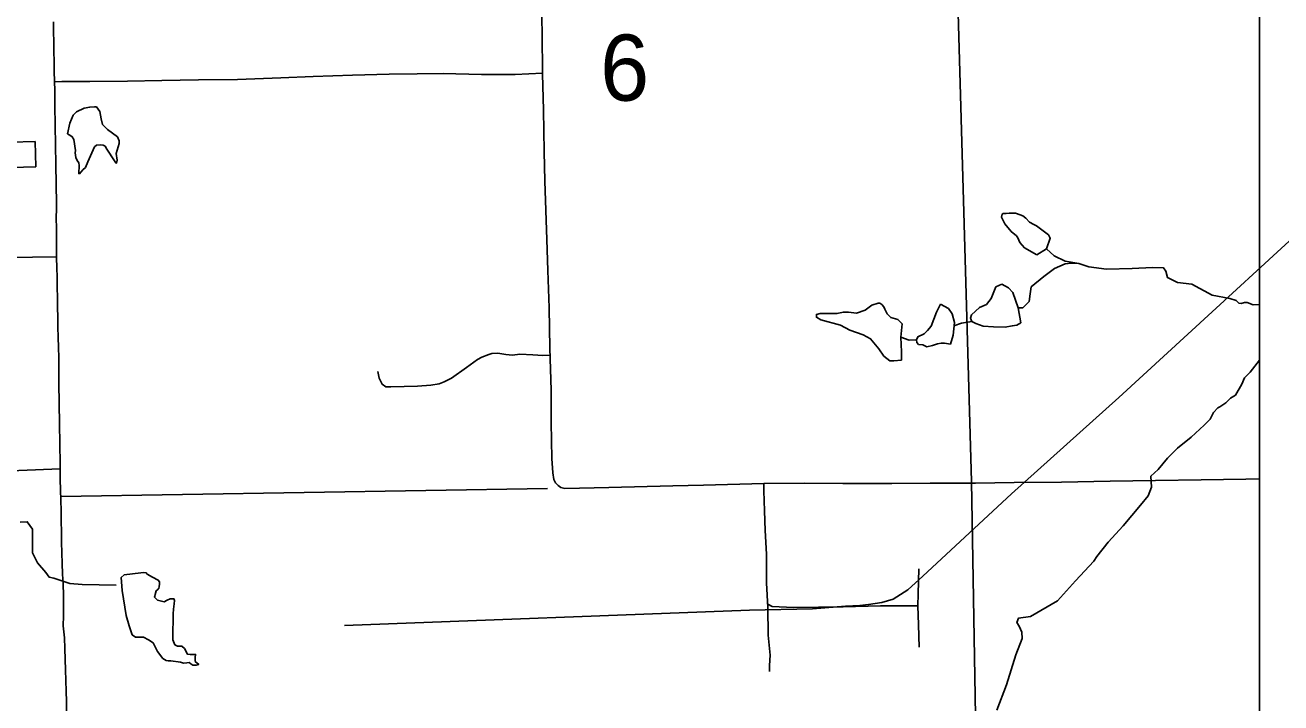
# Model space of a CAD drawing. Extents: x 1367863 to 1368197, y 380048 to 380261.
# Drawn here: x 1368072.73 to 1368103.87, y 380141.12 to 380157.93 of the extents above; entities that cross this region are included whole.
import ezdxf

# ---------------------------------------------------------------- set-up
doc = ezdxf.new("R2010")
doc.units = 0
for name, color, linetype in [('Level 31', 7, 'Continuous'), ('Level 32', 7, 'Continuous'), ('Level 35', 7, 'Continuous'), ('Level 5', 7, 'Continuous'), ('Level 57', 7, 'Continuous'), ('R_Border', 7, 'Continuous'), ('R_No Plot', 7, 'Continuous')]:
    doc.layers.add(name, color=color, linetype=linetype)

msp = doc.modelspace()

# ---------------------------------------------------------------- linework, layer by layer
at = {"layer": 'Level 31'}
msp.add_line((1368073.678, 380143.799), (1368073.678, 380143.799), dxfattribs=at)
for points in [[(1368085.561, 380156.723), (1368085.555, 380157.73), (1368085.526, 380158.785), (1368085.49, 380159.941), (1368085.473, 380160.979), (1368085.455, 380161.56), (1368085.444, 380161.953), (1368085.438, 380163.42), (1368085.432, 380163.836), (1368085.42, 380164.71), (1368085.391, 380165.608), (1368085.373, 380166.665), (1368085.362, 380167.415)], [(1368073.678, 380143.799), (1368073.67, 380144.057), (1368073.658, 380144.32), (1368073.649, 380144.584), (1368073.64, 380144.848), (1368073.635, 380145.109), (1368073.629, 380145.369), (1368073.627, 380145.631), (1368073.623, 380145.889), (1368073.619, 380146.149), (1368073.607, 380146.407), (1368073.601, 380146.666), (1368073.601, 380146.922), (1368073.6, 380147.178), (1368073.593, 380147.423), (1368073.588, 380147.672), (1368073.583, 380147.92), (1368073.579, 380148.169), (1368073.576, 380148.42), (1368073.572, 380148.674), (1368073.568, 380148.929), (1368073.567, 380149.182), (1368073.563, 380149.436), (1368073.562, 380149.689), (1368073.561, 380149.941), (1368073.551, 380150.196), (1368073.545, 380150.442), (1368073.541, 380150.689), (1368073.536, 380150.931), (1368073.535, 380151.176), (1368073.526, 380151.424), (1368073.521, 380151.67), (1368073.516, 380151.917), (1368073.512, 380152.163), (1368073.509, 380152.409), (1368073.506, 380152.654), (1368073.505, 380152.898), (1368073.504, 380153.141), (1368073.507, 380153.381), (1368073.506, 380153.623), (1368073.501, 380153.865), (1368073.498, 380154.108), (1368073.495, 380154.351), (1368073.492, 380154.594), (1368073.487, 380154.838), (1368073.483, 380155.081), (1368073.478, 380155.324), (1368073.473, 380155.567), (1368073.47, 380155.811), (1368073.467, 380156.054), (1368073.469, 380156.303), (1368073.458, 380156.541), (1368073.453, 380156.784), (1368073.453, 380157.035), (1368073.442, 380157.273), (1368073.44, 380157.517), (1368073.437, 380157.763), (1368073.433, 380158.012)], [(1368091.047, 380146.56), (1368089.555, 380146.524), (1368088.797, 380146.51), (1368087.205, 380146.467), (1368086.118, 380146.442), (1368086.015, 380146.466), (1368085.951, 380146.513), (1368085.88, 380146.583), (1368085.842, 380146.662), (1368085.819, 380146.826), (1368085.789, 380147.184), (1368085.775, 380148.073), (1368085.772, 380148.877), (1368085.743, 380149.921), (1368085.725, 380150.918), (1368085.69, 380151.845), (1368085.666, 380152.619), (1368085.619, 380154.058), (1368085.602, 380154.797), (1368085.584, 380155.823), (1368085.561, 380156.723)], [(1368071.348, 380152.148), (1368072.216, 380152.165), (1368072.916, 380152.177), (1368073.512, 380152.189)], [(1368103.344, 380146.677), (1368103.003, 380146.673), (1368101.898, 380146.659), (1368100.761, 380146.638), (1368099.638, 380146.624), (1368098.43, 380146.595), (1368097.254, 380146.588), (1368096.295, 380146.574), (1368095.172, 380146.574), (1368094.22, 380146.567), (1368093.011, 380146.567), (1368092.063, 380146.574), (1368091.047, 380146.56)], [(1368073.758, 380140.894), (1368073.753, 380141.154), (1368073.747, 380141.415), (1368073.739, 380141.677), (1368073.73, 380141.939), (1368073.724, 380142.203), (1368073.716, 380142.472), (1368073.706, 380142.738), (1368073.673, 380143.03), (1368073.68, 380143.281), (1368073.681, 380143.535), (1368073.678, 380143.799)]]:
    msp.add_lwpolyline(points, dxfattribs=at)
at = {"layer": 'Level 32'}
for points in [[(1368085.561, 380156.744), (1368084.879, 380156.708), (1368084.05, 380156.708), (1368083.1, 380156.732), (1368082.454, 380156.72), (1368081.759, 380156.714), (1368080.85, 380156.691), (1368079.877, 380156.656), (1368079.072, 380156.621), (1368078, 380156.586), (1368077.026, 380156.574), (1368076.117, 380156.557), (1368075.269, 380156.545), (1368074.336, 380156.533), (1368073.637, 380156.533), (1368073.458, 380156.527)], [(1368081.474, 380149.341), (1368081.512, 380149.177), (1368081.588, 380149.025), (1368081.676, 380148.962), (1368081.803, 380148.962), (1368082.46, 380148.974), (1368082.789, 380149), (1368082.997, 380149.034), (1368083.12, 380149.086), (1368083.301, 380149.176), (1368083.68, 380149.442), (1368083.951, 380149.637), (1368084.06, 380149.694), (1368084.231, 380149.765), (1368084.307, 380149.784), (1368084.449, 380149.794), (1368084.653, 380149.76), (1368084.815, 380149.746), (1368085, 380149.77), (1368085.318, 380149.756), (1368085.565, 380149.741), (1368085.747, 380149.746)], [(1368091.053, 380146.56), (1368091.047, 380146.381), (1368091.065, 380145.882), (1368091.083, 380145.401), (1368091.114, 380144.81), (1368091.114, 380144.314), (1368091.114, 380144.099), (1368091.15, 380143.489), (1368091.156, 380142.8), (1368091.205, 380142.307), (1368091.193, 380142.051), (1368091.187, 380141.905)], [(1368094.87, 380143.531), (1368094.876, 380143.83), (1368094.894, 380144.445)], [(1368091.149, 380143.574), (1368091.256, 380143.512), (1368091.783, 380143.489), (1368093.013, 380143.507), (1368093.944, 380143.531), (1368094.87, 380143.531)], [(1368094.87, 380143.531), (1368094.888, 380143.056), (1368094.9, 380142.508)]]:
    msp.add_lwpolyline(points, dxfattribs=at)
at = {"layer": 'Level 35'}
for points in [[(1368073.783, 380155.234), (1368073.839, 380155.503), (1368073.922, 380155.698), (1368074.006, 380155.785), (1368074.195, 380155.875), (1368074.334, 380155.899), (1368074.449, 380155.906)], [(1368074.449, 380155.906), (1368074.498, 380155.903), (1368074.582, 380155.788), (1368074.616, 380155.605), (1368074.65, 380155.466), (1368074.777, 380155.345), (1368075.025, 380155.159), (1368075.062, 380155.066), (1368075.059, 380154.995), (1368074.987, 380154.75), (1368075.009, 380154.583), (1368075, 380154.509), (1368074.978, 380154.515), (1368074.944, 380154.564), (1368074.755, 380154.856), (1368074.712, 380154.927), (1368074.665, 380154.955), (1368074.588, 380154.964), (1368074.498, 380154.952), (1368074.449, 380154.911), (1368074.387, 380154.763), (1368074.288, 380154.543), (1368074.229, 380154.403), (1368074.161, 380154.341), (1368074.077, 380154.245), (1368074.058, 380154.252), (1368074.071, 380154.45), (1368074.065, 380154.515), (1368074.024, 380154.577), (1368073.987, 380154.645), (1368073.975, 380154.763), (1368073.978, 380154.825), (1368073.941, 380155.094), (1368073.897, 380155.165), (1368073.86, 380155.19), (1368073.783, 380155.234)], [(1368098.113, 380152.728), (1368097.808, 380152.952), (1368097.747, 380152.986), (1368097.639, 380153.047), (1368097.551, 380153.142), (1368097.469, 380153.203), (1368097.408, 380153.23), (1368097.293, 380153.271), (1368097.205, 380153.271), (1368097.137, 380153.271), (1368097.063, 380153.264), (1368096.988, 380153.257), (1368096.961, 380153.244), (1368096.947, 380153.169), (1368097.029, 380153.006), (1368097.185, 380152.817), (1368097.313, 380152.708), (1368097.347, 380152.654), (1368097.401, 380152.545), (1368097.517, 380152.41), (1368097.822, 380152.234)], [(1368098.113, 380152.728), (1368098.154, 380152.647), (1368098.059, 380152.383), (1368097.822, 380152.234)], [(1368098.059, 380152.383), (1368098.248, 380152.213), (1368098.52, 380152.077), (1368098.865, 380152.017)], [(1368097.354, 380150.918), (1368097.469, 380150.918), (1368097.632, 380151.081), (1368097.652, 380151.264), (1368097.679, 380151.44), (1368097.991, 380151.698), (1368098.262, 380151.895), (1368098.52, 380152.01), (1368098.682, 380152.03), (1368098.865, 380152.017), (1368099.109, 380151.935)], [(1368099.109, 380151.935), (1368099.544, 380151.883), (1368100.181, 380151.896), (1368100.685, 380151.922), (1368100.964, 380151.909), (1368101.017, 380151.83), (1368101.057, 380151.67), (1368101.309, 380151.551), (1368101.667, 380151.511), (1368102.171, 380151.232), (1368102.609, 380151.153), (1368102.766, 380151.105), (1368102.802, 380151.059), (1368102.832, 380151.034), (1368102.89, 380151.032), (1368102.967, 380151.054), (1368103.033, 380151.054), (1368103.185, 380150.996), (1368103.344, 380151.002)], [(1368096.954, 380151.508), (1368096.805, 380151.44), (1368096.69, 380151.156), (1368096.568, 380151.007), (1368096.398, 380150.932), (1368096.202, 380150.749), (1368096.175, 380150.661), (1368096.209, 380150.579), (1368096.304, 380150.532), (1368096.487, 380150.464), (1368096.744, 380150.451), (1368097.035, 380150.444), (1368097.212, 380150.471), (1368097.327, 380150.491), (1368097.422, 380150.546)], [(1368096.954, 380151.508), (1368097.117, 380151.413), (1368097.225, 380151.298), (1368097.354, 380150.918), (1368097.422, 380150.546)], [(1368094.481, 380150.525), (1368094.372, 380150.634), (1368094.196, 380150.681), (1368094.108, 380150.769), (1368094.054, 380150.885), (1368094.027, 380150.946), (1368093.972, 380151.007), (1368093.925, 380151.034), (1368093.884, 380151.04), (1368093.729, 380150.986), (1368093.559, 380150.864), (1368093.349, 380150.79), (1368093.146, 380150.817), (1368093.024, 380150.817), (1368092.861, 380150.776), (1368092.712, 380150.776), (1368092.556, 380150.776), (1368092.448, 380150.776), (1368092.353, 380150.756), (1368092.353, 380150.688), (1368092.461, 380150.627), (1368092.949, 380150.491), (1368093.18, 380150.369), (1368093.512, 380150.254), (1368093.695, 380150.152), (1368093.898, 380149.902), (1368094.027, 380149.725), (1368094.176, 380149.61), (1368094.271, 380149.61), (1368094.467, 380149.624)], [(1368095.429, 380151.013), (1368095.335, 380150.81), (1368095.199, 380150.464), (1368095.111, 380150.356), (1368095.023, 380150.274), (1368094.867, 380150.2), (1368094.833, 380150.125), (1368094.84, 380150.057), (1368094.887, 380150.01), (1368094.996, 380150.003), (1368095.091, 380149.956), (1368095.233, 380149.99), (1368095.355, 380150.03), (1368095.45, 380150.044), (1368095.531, 380150.044), (1368095.68, 380150.017)], [(1368095.429, 380151.013), (1368095.626, 380150.905), (1368095.721, 380150.769), (1368095.775, 380150.559), (1368095.741, 380150.24), (1368095.68, 380150.017)], [(1368094.481, 380150.525), (1368094.447, 380150.193), (1368094.467, 380149.827), (1368094.467, 380149.624)], [(1368095.761, 380150.471), (1368095.951, 380150.539), (1368096.209, 380150.579)], [(1368094.447, 380150.193), (1368094.65, 380150.118), (1368094.833, 380150.125)], [(1368099.232, 380144.64), (1368099.308, 380144.751), (1368099.593, 380145.11), (1368099.96, 380145.51), (1368100.393, 380146.027), (1368100.577, 380146.26), (1368100.66, 380146.477), (1368100.643, 380146.743), (1368100.827, 380146.91), (1368101.06, 380147.194), (1368101.31, 380147.444), (1368101.644, 380147.71), (1368101.968, 380148.01), (1368102.12, 380148.157), (1368102.2, 380148.322), (1368102.31, 380148.442), (1368102.36, 380148.462), (1368102.46, 380148.532), (1368102.51, 380148.567), (1368102.625, 380148.682), (1368102.744, 380148.757), (1368102.904, 380149.026), (1368102.969, 380149.186), (1368103.114, 380149.326), (1368103.344, 380149.621)], [(1368072.61, 380145.601), (1368072.782, 380145.616), (1368072.91, 380145.429), (1368072.91, 380145.229), (1368072.91, 380145), (1368072.91, 380144.843), (1368073.039, 380144.599), (1368073.24, 380144.356), (1368073.325, 380144.241), (1368073.44, 380144.213), (1368073.841, 380144.087), (1368074.141, 380144.058), (1368074.985, 380144.044)], [(1368099.232, 380144.64), (1368098.781, 380144.146), (1368098.33, 380143.652), (1368097.664, 380143.265), (1368097.363, 380143.223), (1368097.321, 380143.115), (1368097.385, 380143.029)], [(1368075.11, 380144.232), (1368075.186, 380144.296), (1368075.602, 380144.348), (1368075.678, 380144.353), (1368075.735, 380144.348), (1368075.759, 380144.319), (1368075.886, 380144.238), (1368076.031, 380144.168), (1368076.065, 380144.128), (1368076.065, 380144.076), (1368076.054, 380144), (1368076.042, 380143.966), (1368076.019, 380143.937), (1368075.979, 380143.902), (1368075.955, 380143.809), (1368075.944, 380143.769), (1368075.938, 380143.745), (1368076.013, 380143.67), (1368076.175, 380143.63), (1368076.256, 380143.67), (1368076.326, 380143.705), (1368076.419, 380143.705), (1368076.436, 380143.659), (1368076.43, 380143.578), (1368076.413, 380143.444), (1368076.401, 380143.334), (1368076.401, 380143.178), (1368076.395, 380142.894), (1368076.395, 380142.686), (1368076.442, 380142.564), (1368076.505, 380142.529), (1368076.615, 380142.529), (1368076.685, 380142.471), (1368076.754, 380142.332), (1368076.824, 380142.327), (1368076.934, 380142.327), (1368076.957, 380142.327), (1368076.951, 380142.251), (1368076.951, 380142.153), (1368077.038, 380142.072), (1368076.974, 380142.055), (1368076.887, 380142.055), (1368076.841, 380142.089), (1368076.795, 380142.124), (1368076.743, 380142.118), (1368076.656, 380142.107), (1368076.581, 380142.13), (1368076.343, 380142.165), (1368076.28, 380142.165), (1368076.228, 380142.176), (1368076.146, 380142.222), (1368076.013, 380142.396), (1368075.903, 380142.61), (1368075.793, 380142.686), (1368075.666, 380142.749), (1368075.544, 380142.749), (1368075.469, 380142.755), (1368075.388, 380142.813)], [(1368075.11, 380144.232), (1368075.133, 380143.908), (1368075.232, 380143.294), (1368075.313, 380143.033), (1368075.388, 380142.813)], [(1368097.385, 380143.029), (1368097.448, 380142.874), (1368097.458, 380142.717), (1368097.301, 380142.316), (1368097.066, 380141.572), (1368096.831, 380140.945)]]:
    msp.add_lwpolyline(points, dxfattribs=at)
at = {"layer": 'Level 5'}
for points in [[(1368095.625, 380166.944), (1368096.197, 380146.617)], [(1368073.601, 380146.926), (1368063.333, 380146.512), (1368053.586, 380146.261)], [(1368096.197, 380146.617), (1368096.554, 380125.803)], [(1368085.687, 380146.444), (1368073.615, 380146.245)]]:
    msp.add_lwpolyline(points, dxfattribs=at)
at = {"layer": 'Level 57'}
msp.add_lwpolyline([(1368072.994, 380154.417), (1368072.388, 380154.402), (1368072.373, 380155.03), (1368072.978, 380155.045)], close=True, dxfattribs=at)
at = {"layer": 'R_Border'}
for points in [[(1368119.33, 380166.4), (1368118.646, 380165.818), (1368118.234, 380165.465), (1368117.744, 380164.97), (1368117.107, 380164.343), (1368108.439, 380156.497), (1368108.18, 380156.313), (1368108.19, 380156.307), (1368107.864, 380155.987), (1368107.805, 380155.903), (1368107.247, 380155.442), (1368106.528, 380154.788), (1368106.296, 380154.621), (1368106.197, 380154.517), (1368099.857, 380148.698), (1368097.192, 380146.307)], [(1368097.192, 380146.307), (1368094.994, 380144.266), (1368094.617, 380143.93), (1368094.442, 380143.815), (1368094.256, 380143.695), (1368093.973, 380143.61), (1368093.649, 380143.56), (1368093.427, 380143.538), (1368093.077, 380143.52), (1368092.26, 380143.454), (1368090.695, 380143.424), (1368080.647, 380143.041)]]:
    msp.add_lwpolyline(points, dxfattribs=at)
at = {"layer": 'R_No Plot'}
msp.add_lwpolyline([(1367959.444, 380177.46), (1368103.344, 380177.46), (1368103.344, 380096.865), (1367959.444, 380096.865)], close=True, dxfattribs=at)

# ---------------------------------------------------------------- texts
at = {"layer": 'Level 5'}
msp.add_text('6', height=1.639, dxfattribs=at).set_placement((1368086.989, 380156.059))

doc.saveas('drawing.dxf')
